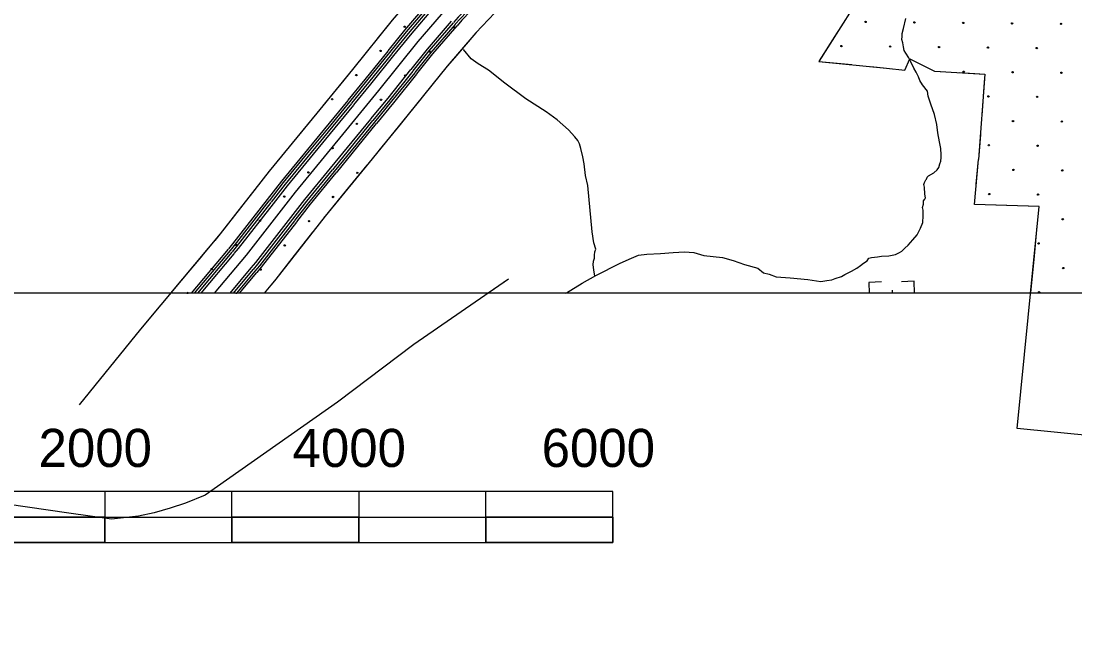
# Model space of a CAD drawing. Extents: x 1577619 to 1828281, y 483481 to 598136.
# Drawn here: x 1681374 to 1689672, y 505510 to 510262 of the extents above; entities that cross this region are included whole.
import ezdxf

# ---------------------------------------------------------------- set-up
doc = ezdxf.new("R2010")
doc.units = 0
for name, color, linetype in [('DESIGN - EROSION CONTROL - Devices', 7, 'Continuous'), ('DESIGN - SHEET - Corner Text', 7, 'Continuous'), ('DESIGN - SHEET - Linework', 7, 'Continuous'), ('DESIGN - TRANSPORTATION - Text', 7, 'Continuous'), ('DESIGN - UTILITIES - Cable (Underground) with Text', 7, 'Continuous'), ('SURVEY - CENTERLINE - Preliminary Text', 7, 'Continuous'), ('SURVEY - CONTROL with Text', 7, 'Continuous'), ('SURVEY - VEGETATION - Features with Text', 7, 'Continuous')]:
    doc.layers.add(name, color=color, linetype=linetype)

msp = doc.modelspace()

# ---------------------------------------------------------------- linework, layer by layer
at = {"layer": 'DESIGN - EROSION CONTROL - Devices'}
for p, q in [((1682679, 508119.9), (1682689.6, 508119.9)), ((1683065.4, 508119.9), (1683072.3, 508119.9))]:
    msp.add_line(p, q, dxfattribs=at)
for centre in [(1688022.9, 510255.4), (1688407.4, 510251.7), (1688792, 510248), (1689176.5, 510244.2), (1684394.3, 510217.9), (1684778.8, 510214.2), (1689561.1, 510240.5), (1684203.9, 510027.5), (1684588.4, 510023.8), (1687832.5, 510065), (1688217, 510061.3), (1688601.6, 510057.6), (1688986.1, 510053.8), (1689370.7, 510050.1), (1684013.4, 509837.1), (1684398, 509833.4), (1688795.7, 509863.4), (1689180.3, 509859.7), (1689564.8, 509856), (1688989.9, 509669.3), (1689374.4, 509665.5), (1683823, 509646.7), (1684207.6, 509642.9), (1684017.2, 509452.5), (1689184, 509475.1), (1689568.6, 509471.4), (1683826.8, 509262.1), (1688993.6, 509284.7), (1689378.1, 509281), (1689187.7, 509090.6), (1689572.3, 509086.9), (1683636.4, 509071.7), (1684020.9, 509068), (1683446, 508881.3), (1683830.5, 508877.6), (1688997.3, 508900.2), (1689381.9, 508896.4), (1683255.5, 508690.9), (1683640.1, 508687.2), (1689576, 508702.3), (1683065.1, 508500.5), (1689385.6, 508511.9), (1683449.7, 508496.8), (1682874.7, 508310.1), (1683259.3, 508306.3), (1689579.8, 508317.7), (1689389.3, 508127.3)]:
    msp.add_circle(centre, 5.28, dxfattribs=at)
for centre, start, end in [((1682684.3, 508119.7), 2.55719, 177.44281), ((1683068.9, 508115.9), 48.73988, 131.26012)]:
    msp.add_arc(centre, 5.28, start, end, dxfattribs=at)
at = {"layer": 'DESIGN - SHEET - Corner Text'}
msp.add_lwpolyline([(1680033.1, 506558.8), (1680033.1, 506158.8), (1686033.1, 506158.8), (1686033.1, 506558.8), (1680033.1, 506558.8), (1680033.1, 506358.8), (1686033.1, 506358.8), (1686033.1, 506158.8), (1685033.1, 506158.8), (1685033.1, 506558.8), (1684033.1, 506558.8), (1684033.1, 506158.8), (1683033.1, 506158.8), (1683033.1, 506558.8), (1682033.1, 506558.8), (1682033.1, 506158.8), (1681033.1, 506158.8), (1681033.1, 506558.8)], dxfattribs=at)
for points in [[(1682033.1, 506358.8), (1683033.1, 506358.8), (1683033.1, 506558.8), (1682033.1, 506558.8)], [(1684033.1, 506358.8), (1685033.1, 506358.8), (1685033.1, 506558.8), (1684033.1, 506558.8)], [(1681033.1, 506158.8), (1682033.1, 506158.8), (1682033.1, 506358.8), (1681033.1, 506358.8)], [(1683033.1, 506158.8), (1684033.1, 506158.8), (1684033.1, 506358.8), (1683033.1, 506358.8)], [(1685033.1, 506158.8), (1686033.1, 506158.8), (1686033.1, 506358.8), (1685033.1, 506358.8)]]:
    msp.add_lwpolyline(points, close=True, dxfattribs=at)
at = {"layer": 'DESIGN - SHEET - Linework'}
msp.add_lwpolyline([(1669171.5, 526510.7), (1695618, 526510.7), (1695618, 508119.9), (1669171.5, 508119.9)], close=True, dxfattribs=at)
at = {"layer": 'DESIGN - TRANSPORTATION - Text'}
for points in [[(1688608.1, 509138.2), (1688616.2, 509160.1), (1688618.4, 509188.2), (1688618.6, 509208.2), (1688617, 509258.2), (1688605.4, 509312.4), (1688591.9, 509382.6), (1688584.4, 509448.7), (1688565.1, 509526.9), (1688537.7, 509609.2), (1688516.3, 509671.5), (1688510.5, 509709.6), (1688471, 509759.9), (1688451.3, 509794.1), (1688439.5, 509822.2), (1688421.9, 509860.4), (1688404.1, 509892.6), (1688378.5, 509940.8), (1688362.8, 509973), (1688341.1, 510009.2), (1688327.3, 510029.4), (1688321.5, 510059.4), (1688315.8, 510091.5), (1688308, 510117.6), (1688312.2, 510139.6), (1688310.4, 510163.6), (1688322.6, 510203.6), (1688341.2, 510281.5)], [(1685891.7, 508254.8), (1685883.1, 508304.7), (1685877.4, 508342.8), (1685881.6, 508372.8), (1685889.8, 508396.8), (1685888, 508420.8), (1685892.1, 508444.8), (1685898.3, 508466.8), (1685882.7, 508517), (1685869.4, 508603.2), (1685836.2, 508967.8), (1685818.8, 509048), (1685807.5, 509138.2), (1685797.9, 509194.4), (1685780.5, 509260.6), (1685770.8, 509296.7), (1685757, 509322.8), (1685733.2, 509351), (1685683.7, 509405.5), (1685594.5, 509484.3), (1685507.2, 509549), (1685348.2, 509650.4), (1685181.5, 509773.8), (1685054.5, 509876.9), (1684973, 509925.6), (1684917.4, 509966.1), (1684858.1, 510038.7)], [(1685664.1, 508119.9), (1685668.2, 508124.3), (1685790.5, 508199.4), (1685898.7, 508258.6), (1686091.1, 508357.2), (1686181.2, 508396.5), (1686235.3, 508420.1), (1686301.2, 508427.6), (1686409, 508432.8), (1686506.9, 508440), (1686596.8, 508447.3), (1686670.6, 508440.7), (1686750.3, 508418), (1686895.9, 508400.9), (1686981.5, 508378.2), (1687071.1, 508347.4), (1687174.7, 508316.6), (1687218.3, 508280.2), (1687264.2, 508269.8), (1687317.9, 508249.4), (1687429.6, 508240.5), (1687567.3, 508227.4), (1687670.9, 508212.6), (1687716.9, 508220.2), (1687756.9, 508225.9), (1687782.9, 508235.7), (1687832.9, 508251.3), (1687859, 508267.2), (1687911.1, 508292.8), (1687955.2, 508316.4), (1687983.3, 508338.3), (1688007.4, 508356.1), (1688035.5, 508375.9), (1688049.6, 508395.8), (1688069.6, 508401.6), (1688117.5, 508407.3), (1688147.5, 508413), (1688207.4, 508414.6), (1688259.4, 508426.2), (1688289.4, 508440), (1688309.5, 508451.8), (1688333.6, 508475.6), (1688359.8, 508499.5), (1688396, 508541.2), (1688428.2, 508581), (1688456.6, 508632.8), (1688472.9, 508676.8), (1688477.2, 508728.8), (1688475.4, 508752.8), (1688477.6, 508774.8), (1688471.8, 508794.9), (1688479.9, 508820.9), (1688478.1, 508846.9), (1688490.2, 508860.8), (1688494.3, 508870.8), (1688488.5, 508898.9), (1688486.9, 508954.9), (1688482.4, 508975.8), (1688487.2, 508993), (1688497.3, 509012.9), (1688503.4, 509018.9), (1688507.5, 509034.9), (1688519.5, 509044.8), (1688559.6, 509068.5), (1688585.8, 509090.3), (1688599.9, 509110.2), (1688608.1, 509138.2)]]:
    msp.add_lwpolyline(points, dxfattribs=at)
at = {"layer": 'DESIGN - UTILITIES - Cable (Underground) with Text'}
for p, q in [((1688048.6, 508205.9), (1688051.7, 508119.9)), ((1688148.3, 508209.4), (1688049.3, 508205.9)), ((1688404.9, 508214.3), (1688305.3, 508210.9)), ((1688408.1, 508119.9), (1688404.8, 508214.3))]:
    msp.add_line(p, q, dxfattribs=at)
msp.add_lwpolyline([(1688231.8, 508144.8), (1688232.7, 508119.9)], dxfattribs=at)
at = {"layer": 'SURVEY - CENTERLINE - Preliminary Text'}
for points in [[(1689584.4, 514616), (1689362.2, 514426), (1688586.1, 513759.5), (1687822.2, 513104.9), (1687187.6, 512557), (1686629.9, 512082.4), (1686078.1, 511605.7), (1685554.7, 511154.7), (1685103.8, 510751), (1684939.9, 510590.5), (1684731.2, 510370.5), (1684498, 510100.6), (1684187.5, 509715.4), (1683905.4, 509369.9), (1683532, 508915.2), (1683146.2, 508420.6), (1682894.1, 508119.9)], [(1685116.7, 510604.2), (1685021.1, 510510.6), (1684815.8, 510294), (1684777.7, 510249.9)], [(1685130.7, 510589.9), (1685035.4, 510496.6), (1684830.6, 510280.6), (1684792.8, 510236.8)], [(1685142.9, 510577.4), (1685047.8, 510484.3), (1684843.6, 510268.8), (1684806.1, 510225.4)], [(1684585.4, 510413.6), (1684391.7, 510189.4), (1684260.9, 510027.2)], [(1684598.7, 510402.2), (1684405.1, 510178.2), (1684274.5, 510016.2)], [(1684613.8, 510389.1), (1684420.5, 510165.4), (1684290.1, 510003.6)], [(1684629.2, 510375.9), (1684436, 510152.4), (1684305.9, 509990.9)], [(1684761.1, 510261.8), (1684570, 510040.6), (1684441.7, 509881.4)], [(1684777.1, 510249.2), (1684585.5, 510027.6), (1684458, 509869.4)], [(1684792.2, 510236.2), (1684600.9, 510014.7), (1684473.6, 509856.8)], [(1684805.5, 510224.7), (1684614.3, 510003.5), (1684487.2, 509845.9)], [(1684260.3, 510026.5), (1684079.9, 509802.7), (1683946, 509638.7)], [(1684274, 510015.5), (1684093.5, 509791.6), (1683959.6, 509627.6)], [(1684289.5, 510002.9), (1684109, 509779), (1683975.1, 509615)], [(1684305.3, 509990.2), (1684124.8, 509766.2), (1683990.8, 509602.2)], [(1684441.1, 509880.7), (1684260.2, 509656.3), (1684125.9, 509491.8)], [(1684457.5, 509868.7), (1684276, 509643.6), (1684142.2, 509479.7)], [(1684473, 509856.1), (1684291.5, 509631), (1684157.7, 509467)], [(1684486.7, 509845.1), (1684305.1, 509619.9), (1684171.2, 509456)], [(1683945.5, 509638), (1683798.2, 509457.7), (1683628.9, 509251.5)], [(1683959, 509626.9), (1683811.8, 509446.6), (1683642.4, 509240.4)], [(1683974.5, 509614.3), (1683827.2, 509433.9), (1683657.9, 509227.7)], [(1683990.2, 509601.4), (1683842.9, 509421), (1683673.6, 509214.8)], [(1684125.3, 509491.1), (1683977.9, 509310.5), (1683808.4, 509104.1)], [(1684141.6, 509479), (1683993.6, 509297.7), (1683824.6, 509091.9)], [(1684157.1, 509466.3), (1684009.1, 509285), (1683840.1, 509079.2)], [(1684170.7, 509455.3), (1684022.6, 509273.9), (1683853.6, 509068.1)], [(1683628.3, 509250.8), (1683423.9, 509001.8), (1683312.3, 508858.8)], [(1683641.8, 509239.7), (1683437.5, 508990.9), (1683326.1, 508848.1)], [(1683657.3, 509227), (1683453.1, 508978.4), (1683341.9, 508835.8)], [(1683673, 509214.1), (1683469, 508965.7), (1683357.9, 508823.3)], [(1683807.8, 509103.4), (1683605.2, 508856.7), (1683495.4, 508716)], [(1683824, 509091.2), (1683621, 508844), (1683512, 508704.2)], [(1683839.5, 509078.5), (1683636.6, 508831.5), (1683527.7, 508691.9)], [(1683853, 509067.4), (1683650.3, 508820.6), (1683541.5, 508681.2)], [(1683311.8, 508858.1), (1683038.5, 508507.8), (1683005.8, 508468.9)], [(1683325.6, 508847.4), (1683052.1, 508496.8), (1683019.3, 508457.6)], [(1683341.4, 508835.1), (1683067.6, 508484.2), (1683034.6, 508444.8)], [(1683357.3, 508822.6), (1683083.4, 508471.4), (1683050.1, 508431.7)], [(1683494.9, 508715.3), (1683219, 508361.7), (1683183.8, 508319.7)], [(1683511.4, 508703.5), (1683234.8, 508349), (1683199.9, 508307.3)], [(1683527.2, 508691.2), (1683250.4, 508336.4), (1683215.3, 508294.5)], [(1683541, 508680.5), (1683264, 508325.4), (1683228.7, 508283.3)], [(1683005.3, 508468.2), (1682713.4, 508119.9)], [(1683018.7, 508456.9), (1682736.2, 508119.9)], [(1683034, 508444.1), (1682762.3, 508119.9)], [(1683049.6, 508431), (1682788.8, 508119.9)], [(1683183.2, 508319), (1683016.4, 508119.9)], [(1683199.4, 508306.6), (1683042.8, 508119.9)], [(1683214.7, 508293.8), (1683068.9, 508119.9)], [(1683228.1, 508282.6), (1683091.8, 508119.9)]]:
    msp.add_lwpolyline(points, dxfattribs=at)
at = {"layer": 'SURVEY - CONTROL with Text'}
for points in [[(1685212, 508230.8), (1684466.5, 507717.3), (1683864.4, 507261.8), (1682823.3, 506530.2), (1682667.7, 506466.7), (1682547.1, 506427.7), (1682420.6, 506392.7), (1682297.8, 506365.7), (1682085.5, 506341.2), (1681750, 506389), (1681262.7, 506460.5), (1681163.7, 506472.5), (1681074.2, 506478.3), (1680971.1, 506470.5), (1680858.9, 506455.6), (1679631, 506236.7), (1679564.8, 506213.4), (1679293, 506030.1), (1678660.7, 505558.7), (1678619.6, 505507.6)], [(1685212, 508230.8), (1685051, 508119.9)]]:
    msp.add_lwpolyline(points, dxfattribs=at)
at = {"layer": 'SURVEY - VEGETATION - Features with Text'}
for points in [[(1689413.1, 514816.5), (1689190.6, 514626.4), (1688414.4, 513959.7), (1687650.2, 513304.9), (1687015.9, 512757.3), (1686458.2, 512282.6), (1685905.8, 511805.4), (1685380.6, 511352.9), (1684923.5, 510943.6), (1684751.9, 510775.6), (1684535.6, 510547.6), (1684295.5, 510269.6), (1683982.7, 509881.6), (1683701.3, 509537), (1683326.1, 509080.1), (1682941.1, 508586.5), (1682313.7, 507838), (1681830.8, 507240.7)], [(1689413.1, 514816.5), (1689190.6, 514626.4), (1688414.4, 513959.7), (1687650.2, 513304.9), (1687015.9, 512757.3), (1686458.2, 512282.6), (1685905.8, 511805.4), (1685380.6, 511352.9), (1684923.5, 510943.6), (1684751.9, 510775.6), (1684535.6, 510547.6), (1684295.5, 510269.6), (1683982.7, 509881.6), (1683701.3, 509537), (1683326.1, 509080.1), (1682941.1, 508586.5), (1682313.7, 507838), (1681830.8, 507240.7)], [(1689413.1, 514816.5), (1689190.6, 514626.4), (1688414.4, 513959.7), (1687650.2, 513304.9), (1687015.9, 512757.3), (1686458.2, 512282.6), (1685905.8, 511805.4), (1685380.6, 511352.9), (1684923.5, 510943.6), (1684751.9, 510775.6), (1684535.6, 510547.6), (1684295.5, 510269.6), (1683982.7, 509881.6), (1683701.3, 509537), (1683326.1, 509080.1), (1682941.1, 508586.5), (1682550, 508119.9)], [(1689413.1, 514816.5), (1689190.6, 514626.4), (1688414.4, 513959.7), (1687650.2, 513304.9), (1687015.9, 512757.3), (1686458.2, 512282.6), (1685905.8, 511805.4), (1685380.6, 511352.9), (1684923.5, 510943.6), (1684751.9, 510775.6), (1684535.6, 510547.6), (1684295.5, 510269.6), (1683982.7, 509881.6), (1683701.3, 509537), (1683326.1, 509080.1), (1682941.1, 508586.5), (1682550, 508119.9)], [(1689413.1, 514816.5), (1689190.6, 514626.4), (1688414.4, 513959.7), (1687650.2, 513304.9), (1687015.9, 512757.3), (1686458.2, 512282.6), (1685905.8, 511805.4), (1685380.6, 511352.9), (1684923.5, 510943.6), (1684751.9, 510775.6), (1684535.6, 510547.6), (1684295.5, 510269.6), (1683982.7, 509881.6), (1683701.3, 509537), (1683326.1, 509080.1), (1682941.1, 508586.5), (1682550, 508119.9)], [(1686776.6, 511811.5), (1686274.7, 511377.8), (1685753.2, 510928.6), (1685309.5, 510531.3), (1685154.4, 510379.4), (1684954.4, 510168.5), (1684729.1, 509907.7), (1684421.2, 509525.8), (1684138.2, 509179.2), (1683767, 508727.2), (1683380.2, 508231.4), (1683286.8, 508119.9)], [(1686776.6, 511811.5), (1688173.7, 510764.8), (1687655.5, 509945.2), (1688186.8, 509892.3)], [(1684342, 510323.4), (1684295.5, 510269.6), (1684174.4, 510119.4)], [(1684959.2, 510173.5), (1684954.4, 510168.5), (1684786.4, 509974)], [(1687798.4, 510171.2), (1687657.3, 509948.1)], [(1684080.3, 510002.6), (1683982.7, 509881.6), (1683914.1, 509797.5)], [(1684786.4, 509974), (1684729.1, 509907.7), (1684618.4, 509770.4)], [(1687657.3, 509948.1), (1687655.5, 509945.2), (1687914.8, 509919.4)], [(1688186.8, 509892.3), (1688333.2, 509876), (1688372.3, 509964.1)], [(1688186.8, 509892.3), (1688333.2, 509876), (1688372.3, 509964.1)], [(1688372.3, 509964.1), (1688565.7, 509867.3), (1688962.3, 509845.4), (1688912.4, 509173.3)], [(1688372.3, 509964.1), (1688565.7, 509867.3), (1688613.4, 509864.7)], [(1688064, 509904.5), (1688186.8, 509892.3)], [(1688763.1, 509856.4), (1688962.3, 509845.4), (1688957.6, 509781.1)], [(1683914.1, 509797.5), (1683747.1, 509593.1)], [(1688957.6, 509781.1), (1688938, 509517.9)], [(1684524.2, 509653.6), (1684421.2, 509525.8), (1684358.1, 509448.5)], [(1683652.1, 509477), (1683484.5, 509273)], [(1684358.1, 509448.5), (1684191.1, 509244)], [(1688926.9, 509368.3), (1688912.4, 509173.3)], [(1683484.5, 509273), (1683326.1, 509080.1), (1683317.2, 509068.7)], [(1691041.7, 501626.2), (1691085.7, 501868.9), (1692192.2, 501688.4), (1692388.4, 503210.9), (1692518.7, 504240.9), (1690995.6, 504460.8), (1690892.1, 505470.1), (1690752.9, 506903.5), (1689217, 507055.6), (1689391, 508804.1), (1688880.6, 508817.3), (1688912.4, 509173.3)], [(1691041.7, 501626.2), (1691085.7, 501868.9), (1692192.2, 501688.4), (1692388.4, 503210.9), (1692518.7, 504240.9), (1690995.6, 504460.8), (1690892.1, 505470.1), (1690752.9, 506903.5), (1689217, 507055.6), (1689391, 508804.1), (1688880.6, 508817.3), (1688912.4, 509173.3)], [(1689322.9, 508119.9), (1689391, 508804.1), (1688880.6, 508817.3), (1688912.4, 509173.3)], [(1689322.9, 508119.9), (1689391, 508804.1), (1688880.6, 508817.3), (1688912.4, 509173.3)], [(1689322.9, 508119.9), (1689391, 508804.1), (1688880.6, 508817.3), (1688912.4, 509173.3)], [(1688895, 508978.4), (1688912.4, 509173.3)], [(1684096.1, 509127.9), (1683928.5, 508923.9)], [(1683225, 508950.5), (1683062.6, 508742.3)], [(1683928.5, 508923.9), (1683767, 508727.2), (1683761.2, 508719.7)], [(1689132.7, 508810.7), (1688880.6, 508817.3), (1688881.7, 508829)], [(1689390.4, 508798.4), (1689391, 508804.1), (1689132.7, 508810.7)], [(1683062.6, 508742.3), (1682941.1, 508586.5), (1682898.4, 508535.6)], [(1683668.9, 508601.4), (1683506.5, 508393.3)], [(1689349.4, 508386.4), (1689375.6, 508649.1)], [(1682802.1, 508420.7), (1682632.5, 508218.3)], [(1683506.5, 508393.3), (1683380.2, 508231.4), (1683342.5, 508186.4)], [(1689323.3, 508123.7), (1689349.4, 508386.5)], [(1682632.5, 508218.3), (1682550, 508119.9)]]:
    msp.add_lwpolyline(points, dxfattribs=at)

# ---------------------------------------------------------------- texts
at = {"layer": 'DESIGN - SHEET - Corner Text'}
for s, p in [('2000', (1681511.3, 506752.8)), ('4000', (1683511.3, 506752.8)), (' 6000', (1685361.3, 506752.8))]:
    msp.add_text(s, height=300, dxfattribs=at).set_placement(p)

doc.saveas('drawing.dxf')
